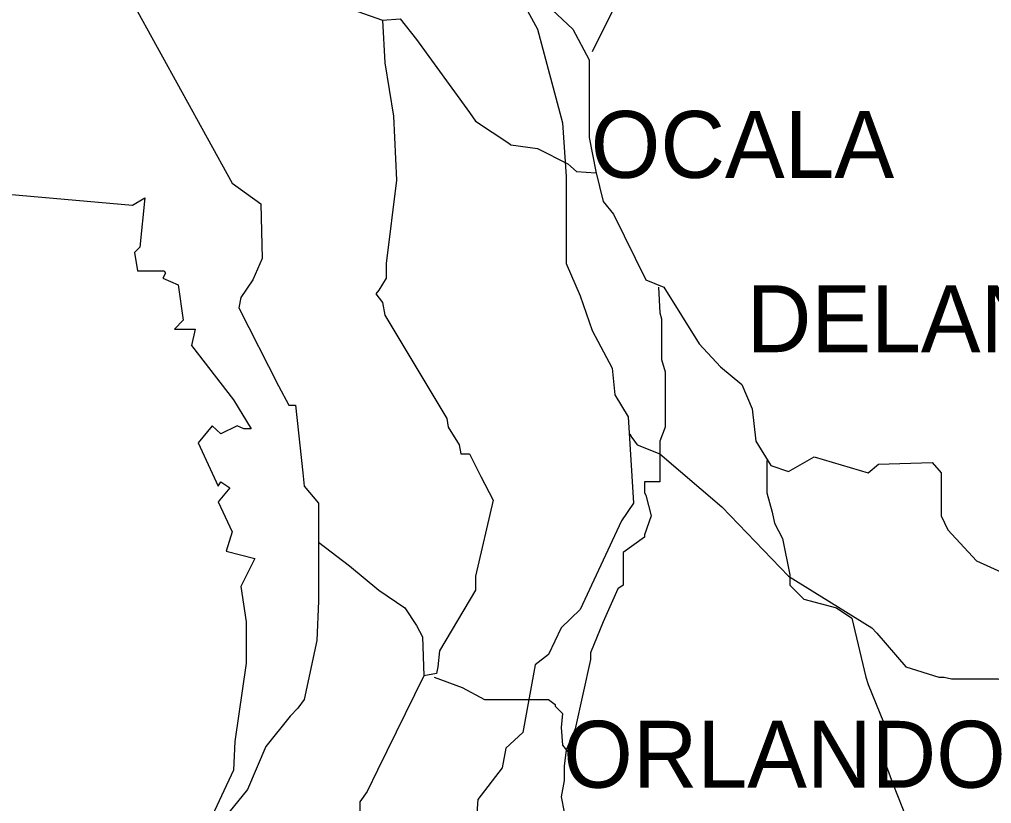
# Model space of a CAD drawing. Extents: x -827.9 to -798.1, y -2199.1 to -2182.2.
# Drawn here: x -806.443 to -805.79, y -2184.436 to -2183.909 of the extents above; entities that cross this region are included whole.
import ezdxf

# ---------------------------------------------------------------- set-up
doc = ezdxf.new("R2010")
doc.units = 0
for name, color, linetype in [('FLMap2', 7, 'Continuous'), ('FLMap3', 7, 'Continuous'), ('TextMisc', 7, 'Continuous')]:
    doc.layers.add(name, color=color, linetype=linetype)

msp = doc.modelspace()

# ---------------------------------------------------------------- linework, layer by layer
at = {"layer": 'FLMap2'}
for points in [[(-806.05815, -2183.64272), (-806.06609, -2183.66802), (-806.06956, -2183.67497), (-806.06857, -2183.70176), (-806.05815, -2183.71119), (-806.05666, -2183.7345), (-806.03384, -2183.79007), (-806.03036, -2183.80049), (-806.03632, -2183.8243), (-806.03731, -2183.85655), (-806.04277, -2183.89971), (-806.05815, -2183.93047)], [(-806.64109, -2183.76923), (-806.63514, -2183.80297), (-806.63712, -2183.80198), (-806.63365, -2183.84514), (-806.58354, -2183.88136), (-806.58503, -2183.88682), (-806.55824, -2183.88781), (-806.52401, -2183.94883), (-806.52897, -2183.95726), (-806.4868, -2183.97711), (-806.47638, -2183.99199), (-806.48432, -2183.99993), (-806.47489, -2184.02623), (-806.45108, -2184.02623), (-806.36723, -2184.03367), (-806.3588, -2184.02871), (-806.36227, -2184.06195)], [(-806.3841, -2183.85804), (-806.37567, -2183.86399), (-806.30422, -2183.86251), (-806.29083, -2183.87342), (-806.27297, -2183.88285), (-806.19905, -2183.90914), (-806.18714, -2183.90815), (-806.17622, -2183.92204), (-806.1405, -2183.97116), (-806.13653, -2183.97711), (-806.11421, -2183.99199), (-806.11272, -2183.99299), (-806.09486, -2183.99547), (-806.07452, -2184.00588), (-806.06857, -2184.01085), (-806.05567, -2184.01184)], [(-806.3841, -2183.86598), (-806.30026, -2184.01878), (-806.28091, -2184.03268), (-806.27991, -2184.06939), (-806.28636, -2184.08378), (-806.2943, -2184.09568), (-806.29579, -2184.10263), (-806.269, -2184.15522), (-806.26205, -2184.16812), (-806.25759, -2184.16812), (-806.25263, -2184.21376), (-806.25164, -2184.22269), (-806.24221, -2184.2341), (-806.24221, -2184.30009)], [(-806.08494, -2183.90219), (-806.07105, -2183.91509), (-806.06013, -2183.93593), (-806.06013, -2183.98802), (-806.05567, -2184.01085), (-806.05071, -2184.03119), (-806.04376, -2184.03962), (-806.02193, -2184.08378), (-806.01002, -2184.08874), (-805.98621, -2184.12694), (-805.97182, -2184.14232), (-805.95743, -2184.15423), (-805.95049, -2184.1706), (-805.94801, -2184.19243), (-805.93808, -2184.2088), (-805.92618, -2184.21277), (-805.90881, -2184.20285), (-805.8726, -2184.21376), (-805.86565, -2184.20781), (-805.82943, -2184.20682), (-805.82348, -2184.21376), (-805.82348, -2184.24254), (-805.81902, -2184.25196), (-805.79967, -2184.2728), (-805.77139, -2184.2857)], [(-806.19905, -2183.90914), (-806.19756, -2183.93792), (-806.1916, -2183.97364), (-806.18962, -2184.0168), (-806.19657, -2184.07286), (-806.19657, -2184.08278), (-806.20153, -2184.09072), (-806.20351, -2184.0932), (-806.19905, -2184.09916), (-806.19756, -2184.10759), (-806.15588, -2184.17705), (-806.15489, -2184.183), (-806.14745, -2184.19491), (-806.14646, -2184.20086), (-806.1405, -2184.20086), (-806.13306, -2184.21624), (-806.12463, -2184.23212), (-806.13653, -2184.28322), (-806.13653, -2184.28917)], [(-806.36227, -2184.06195), (-806.36574, -2184.06542), (-806.36376, -2184.07782), (-806.3459, -2184.07782), (-806.34491, -2184.07931), (-806.34689, -2184.08278), (-806.33647, -2184.08725), (-806.333, -2184.11106), (-806.33895, -2184.11702), (-806.32506, -2184.11702), (-806.32754, -2184.12793), (-806.29926, -2184.16464), (-806.28736, -2184.18399), (-806.29232, -2184.18399), (-806.29678, -2184.18201), (-806.3077, -2184.18747), (-806.31365, -2184.18201), (-806.32308, -2184.19342), (-806.30968, -2184.22269), (-806.3077, -2184.21971), (-806.30174, -2184.22368), (-806.30968, -2184.23311), (-806.30026, -2184.25345), (-806.30422, -2184.26635), (-806.28488, -2184.27131), (-806.2943, -2184.29016), (-806.29083, -2184.31398), (-806.29083, -2184.34176)], [(-806.0135, -2184.08874), (-806.0125, -2184.1061), (-806.01151, -2184.11007)], [(-806.01151, -2184.11007), (-806.01151, -2184.13736), (-806.00903, -2184.14579), (-806.00903, -2184.183), (-806.0125, -2184.19243), (-806.0125, -2184.21723), (-806.0125, -2184.21971), (-806.02292, -2184.21971), (-806.02292, -2184.22716), (-806.02193, -2184.22864), (-806.01846, -2184.24254), (-806.02292, -2184.25544), (-806.02292, -2184.25692), (-806.03731, -2184.26734), (-806.03731, -2184.28917), (-806.04078, -2184.29165), (-806.05071, -2184.31398), (-806.05914, -2184.33482), (-806.05914, -2184.33928), (-806.06956, -2184.38592), (-806.07551, -2184.4003), (-806.077, -2184.41072), (-806.077, -2184.42065), (-806.07898, -2184.43156), (-806.077, -2184.44198)], [(-805.94057, -2184.20533), (-805.94057, -2184.22716), (-805.93709, -2184.24006), (-805.9356, -2184.2475), (-805.93015, -2184.25792), (-805.92519, -2184.28223), (-805.92519, -2184.28917), (-805.91576, -2184.2986), (-805.89393, -2184.30455), (-805.88351, -2184.3115), (-805.87408, -2184.35119), (-805.8726, -2184.35615), (-805.86218, -2184.38145), (-805.86218, -2184.38939), (-805.86416, -2184.4003), (-805.85622, -2184.42213), (-805.84283, -2184.45637), (-805.8334, -2184.51044), (-805.82596, -2184.52483), (-805.82497, -2184.55956)], [(-806.24221, -2184.2604), (-806.22137, -2184.27627), (-806.20153, -2184.29264), (-806.18416, -2184.30455), (-806.17622, -2184.31646), (-806.17226, -2184.3239), (-806.17126, -2184.3502)], [(-806.13653, -2184.28917), (-806.13653, -2184.29264), (-806.16084, -2184.33333), (-806.16184, -2184.34424), (-806.16283, -2184.34871), (-806.17126, -2184.3502), (-806.20252, -2184.4137), (-806.20946, -2184.42809), (-806.21443, -2184.43503), (-806.21443, -2184.44198), (-806.22137, -2184.45389), (-806.22038, -2184.46282), (-806.22038, -2184.46976), (-806.22137, -2184.47571), (-806.2179, -2184.48167), (-806.20599, -2184.50499), (-806.20153, -2184.51044), (-806.19905, -2184.52483), (-806.20351, -2184.5422), (-806.20004, -2184.54964), (-806.20153, -2184.57246), (-806.20004, -2184.58189), (-806.19657, -2184.59032)], [(-806.24221, -2184.30009), (-806.24221, -2184.30009), (-806.2432, -2184.32638), (-806.25164, -2184.36607), (-806.2561, -2184.37202), (-806.26106, -2184.37748), (-806.27743, -2184.39782), (-806.28984, -2184.4266), (-806.31117, -2184.45289), (-806.31117, -2184.4782), (-806.32407, -2184.49953), (-806.32407, -2184.50052), (-806.32407, -2184.5164), (-806.32903, -2184.5283), (-806.33052, -2184.54368)], [(-806.29083, -2184.34176), (-806.29827, -2184.39435), (-806.29926, -2184.4137), (-806.32506, -2184.46877), (-806.33151, -2184.49705), (-806.33498, -2184.51292), (-806.34094, -2184.51292), (-806.34094, -2184.51888), (-806.33498, -2184.51987), (-806.35533, -2184.54021), (-806.35632, -2184.5422), (-806.34342, -2184.5541), (-806.34243, -2184.55658), (-806.35284, -2184.54964), (-806.35781, -2184.54964), (-806.34689, -2184.58189)], [(-806.16432, -2184.35119), (-806.14546, -2184.35813), (-806.13058, -2184.36607), (-806.08742, -2184.36607), (-806.08295, -2184.36954), (-806.08295, -2184.37054), (-806.07799, -2184.3755), (-806.07898, -2184.38492), (-806.07799, -2184.39683), (-806.07452, -2184.4013)]]:
    msp.add_lwpolyline(points, dxfattribs=at)
at = {"layer": 'FLMap3'}
for points in [[(-806.10826, -2183.89029), (-806.09486, -2183.91509), (-806.07799, -2183.9781), (-806.07551, -2184.01432), (-806.07551, -2184.07286), (-806.06609, -2184.09469), (-806.05815, -2184.11801), (-806.04475, -2184.14331), (-806.04277, -2184.16117), (-806.03384, -2184.17606), (-806.03036, -2184.2341), (-806.0383, -2184.24601), (-806.06609, -2184.30554), (-806.07898, -2184.31795), (-806.08742, -2184.33581), (-806.09635, -2184.34275), (-806.10478, -2184.3884), (-806.11619, -2184.39882), (-806.11867, -2184.41221), (-806.13505, -2184.43354), (-806.13951, -2184.49457)], [(-806.03284, -2184.18747), (-806.03136, -2184.18995), (-806.02788, -2184.19491), (-806.0125, -2184.20086), (-805.98472, -2184.22468), (-805.97083, -2184.23658), (-805.92618, -2184.28322), (-805.87012, -2184.31795), (-805.86664, -2184.32142), (-805.84729, -2184.34424), (-805.82497, -2184.35119), (-805.8215, -2184.35119), (-805.81653, -2184.35218), (-805.78528, -2184.35218), (-805.78081, -2184.35367), (-805.77734, -2184.35813)]]:
    msp.add_lwpolyline(points, dxfattribs=at)

# ---------------------------------------------------------------- texts
at = {"layer": 'TextMisc'}
for s, p in [('OCALA', (-806.05906, -2184.01523)), ('DELAND', (-805.95416, -2184.13251)), ('ORLANDO', (-806.07757, -2184.4255))]:
    msp.add_text(s, height=0.045, dxfattribs=at).set_placement(p)

doc.saveas('drawing.dxf')
